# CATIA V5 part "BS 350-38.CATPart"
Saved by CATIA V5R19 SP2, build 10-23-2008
Part number: BS 300-38
Bounding box of the stored display mesh (mm): x -15.868 to 15.868, y -15.868 to 15.868, z 0 to 106
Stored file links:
  C:\Users\Bora\Desktop\3D Katı model\BS serisi\BS 300\BS 300-38.CATPart
  C:\Program Files\Dassault Systemes\B19\intel_a\reffiles\standard\MetricThickPitch.txt
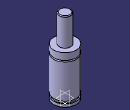
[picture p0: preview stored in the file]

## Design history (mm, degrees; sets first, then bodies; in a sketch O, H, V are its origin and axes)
Body1 (main body)
  Sketch1 on yz-plane, origin (0, 0, 0), H (0, 1, 0), V (0, 0, 1)
    point P1 (8, 105)
    point P3 (8, 105)
    point P5 (16, 57.5)
    point P6 (16, 55.5)
    point P9 (16, 57.5)
    point P14 (16, 55.5)
    line L1 (8, 105) -> (8, 67)
    arc A1 centre (7, 105) radius 1 from (8, 105) to (7, 106) ccw
    arc A2 centre (16, 56.5) radius 1 from (16, 57.5) to (16, 55.5) ccw
    line L2 (16, 0) -> (16, 4)
    line L3 (16, 57.5) -> (16, 67)
    line L4 (14.5, 7.5) -> (14.5, 4)
    line L5 (16, 7.5) -> (16, 55.5)
    line L6 (7, 106) -> (0, 106)
    point P15 (0, 106)
    line L7 (8, 67) -> (16, 67)
    line L8 (0, 0) -> (16, 0)
    line L9 (14.5, 7.5) -> (16, 7.5)
    line L10 (14.5, 4) -> (16, 4)
    coincidence: P15 V, P1 P3, P5 P9, P6 P14
    tangency: L6 A1
    horizontal: L7 H, L8 H, L9 H, L10 H
  Shaft1: profile Sketch1, axis Sketch1.V, angle 360
  Sketch2 on face of Shaft1 from Sketch1.L8, origin (0, 0, 0), H (1, 0, 0), V (0, -1, 0)
    point P1 (0, 0)
  Hole1: placed by Sketch2, at (0, 0, 0) direction (0, 0, 1), diameter 6.647, depth 4, threaded "M8", thread diameter 8, thread depth 4, pitch 1.25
